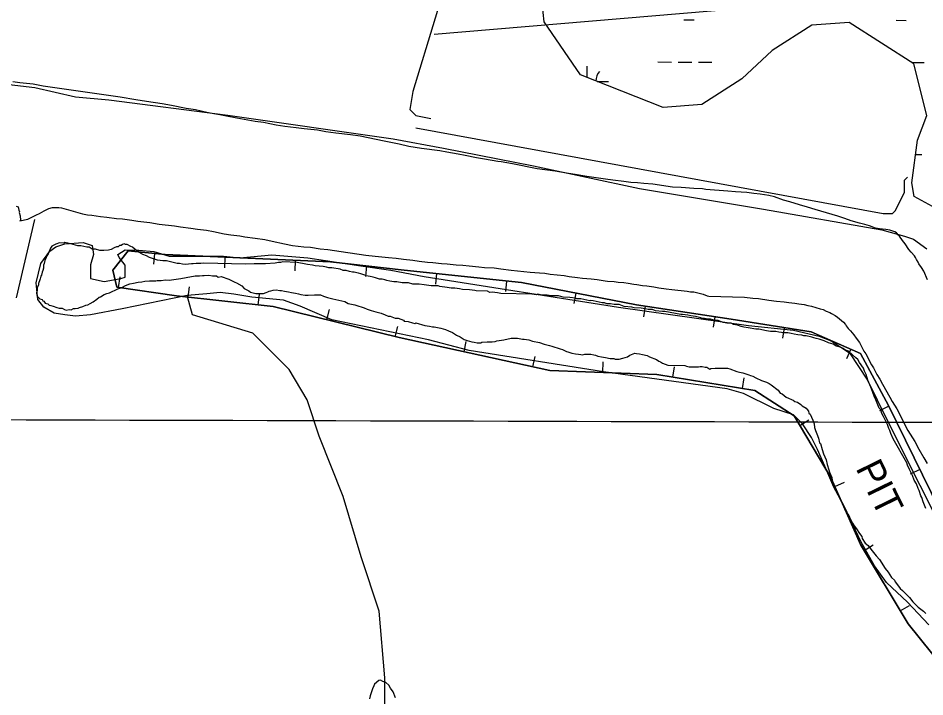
# Model space of a CAD drawing. Extents: x 3172297 to 3210190, y 958463 to 983887.
# Drawn here: x 3182176 to 3184322, y 975375 to 976980 of the extents above; entities that cross this region are included whole.
import ezdxf

# ---------------------------------------------------------------- set-up
doc = ezdxf.new("R2010")
doc.units = 0
for name, color, linetype in [('V-BORW-LINE', 7, 'Continuous'), ('V-GRID-MAJR', 7, 'Continuous'), ('V-RIVR-RANG', 7, 'Continuous'), ('V-SITE-VEGE', 7, 'Continuous'), ('V-TOPO-SHOR', 7, 'Continuous'), ('V-WETL-SWMP', 7, 'Continuous')]:
    doc.layers.add(name, color=color, linetype=linetype)

msp = doc.modelspace()

# ---------------------------------------------------------------- linework, layer by layer
at = {"layer": 'V-BORW-LINE'}
for p, q in [((3182498.8, 976423.5), (3182496.2, 976398.6)), ((3182665.1, 976414.7), (3182664, 976389.7)), ((3182831.6, 976407.4), (3182830.5, 976382.4)), ((3183000.7, 976394.1), (3182998, 976369.3)), ((3182413.6, 976343.3), (3182417.2, 976368.1)), ((3183166.3, 976376), (3183163.7, 976351.2)), ((3183332, 976358.4), (3183329.4, 976333.6)), ((3182578.5, 976320.1), (3182581.3, 976344.9)), ((3182744.1, 976301.8), (3182746.9, 976326.6)), ((3183496, 976329.7), (3183491.2, 976305.1)), ((3183659.7, 976298.8), (3183656, 976274.1)), ((3182906.7, 976266.6), (3182912.7, 976290.9)), ((3183824.5, 976274), (3183820.7, 976249.3)), ((3183068.5, 976226.8), (3183074.5, 976251.1)), ((3183989, 976248.1), (3183985.1, 976223.4)), ((3183231.2, 976191.2), (3183236.6, 976215.6)), ((3184146.3, 976197.1), (3184136.3, 976174.2)), ((3183394, 976155.8), (3183399.4, 976180.2)), ((3183559.6, 976142.1), (3183560.6, 976167.1)), ((3183725.6, 976130.9), (3183729.6, 976155.6)), ((3183890.1, 976104.5), (3183894.1, 976129.2)), ((3184236.6, 976062.6), (3184214.2, 976051.6)), ((3184025.7, 976017), (3184047.2, 976029.8)), ((3184309.6, 975912.8), (3184287.2, 975901.9)), ((3184108.7, 975872.7), (3184131.5, 975882.8)), ((3184178, 975721.3), (3184199.4, 975734.2)), ((3184263.6, 975578.4), (3184285, 975591.2))]:
    msp.add_line(p, q, dxfattribs=at)
for points in [[(3184396, 975406.6), (3184281.9, 975547.8), (3184169.7, 975735.2), (3184100, 975892.1), (3184012.5, 976039.3), (3183919.6, 976099.8), (3183687.3, 976137), (3183433.9, 976147.1), (3183078, 976224.5), (3182779.5, 976297.9), (3182551.1, 976323.1), (3182409.4, 976343.9), (3182400, 976383.8), (3182436.6, 976429.9), (3182524, 976420.9), (3182914.8, 976403.7)], [(3182914.8, 976403.7), (3182524, 976420.9), (3182436.6, 976429.9), (3182400, 976383.8), (3182409.4, 976343.9), (3182551.1, 976323.1), (3182779.5, 976297.9), (3183078, 976224.5), (3183433.9, 976147.1), (3183687.3, 976137), (3183919.6, 976099.8), (3184012.5, 976039.3), (3184100, 975892.1), (3184169.7, 975735.2), (3184281.9, 975547.8), (3184396, 975406.6)], [(3182914.8, 976403.7), (3183089.3, 976384.2), (3183367, 976354.7), (3183639.1, 976301.9), (3183863.3, 976268.1), (3184052.4, 976238), (3184169.3, 976187.1), (3184235.8, 976064.2), (3184336.3, 975858.1), (3184474.4, 975546.9), (3184589.7, 975345.9), (3184718, 975116), (3184852.9, 974871.7), (3184939.5, 974677.4), (3185118.5, 974284.7), (3185285.5, 973986.3), (3185406.5, 973754.8)], [(3185406.5, 973754.8), (3185285.5, 973986.3), (3185118.5, 974284.7), (3184939.5, 974677.4), (3184852.9, 974871.7), (3184718, 975116), (3184589.7, 975345.9), (3184474.4, 975546.9), (3184336.3, 975858.1), (3184235.8, 976064.2), (3184169.3, 976187.1), (3184052.4, 976238), (3183863.3, 976268.1), (3183639.1, 976301.9), (3183367, 976354.7), (3183089.3, 976384.2), (3182914.8, 976403.7)]]:
    msp.add_lwpolyline(points, dxfattribs=at)
at = {"layer": 'V-GRID-MAJR'}
msp.add_spline([(3176574.9, 976046.2), (3181787.8, 976031.4), (3187000.7, 976017.3), (3192213.6, 976004.1), (3197426.5, 975991.6), (3202639.4, 975979.8), (3207852.4, 975968.8)], degree=3, dxfattribs=at)
at = {"layer": 'V-SITE-VEGE'}
for points in [[(3182653.4, 976751.8), (3182639.3, 976754.2), (3182622.2, 976757.5), (3182595.7, 976763.1), (3182573.8, 976766.4), (3182538.7, 976773.6), (3182516.9, 976777.7), (3182479.5, 976783.4), (3182454.5, 976787.5), (3182417.1, 976793.2), (3182235.3, 976819.4), (3182211.2, 976824.2), (3182180, 976827.5), (3182163.6, 976830)], [(3184327.8, 976361.3), (3184319.4, 976381.7), (3184313.9, 976390.3), (3184307.8, 976398.9), (3184306.2, 976402.8), (3184301.6, 976409.1), (3184299.3, 976413.8), (3184297, 976417.7), (3184289.2, 976427.1), (3184283.8, 976433.4), (3184275.3, 976446.7), (3184269.1, 976454.6), (3184262.1, 976464.8), (3184259, 976467.1), (3184254.4, 976472.6), (3184250.5, 976475), (3184238.8, 976479), (3184229.4, 976480.6), (3184214.6, 976482.3), (3184205.3, 976483.9), (3184190.5, 976488.7), (3184179.6, 976491.9), (3184167.1, 976495.1), (3184147.6, 976500.7), (3184132, 976506.2), (3184115.7, 976511.8), (3184089.2, 976519.8), (3184061.9, 976527.8), (3184044, 976533.4), (3184025.3, 976539), (3184001.9, 976546.1), (3183987.1, 976550.1), (3183966.1, 976557.3), (3183952.8, 976560.5), (3183931.8, 976563.8), (3183916.9, 976565.4), (3183900.6, 976567.9), (3183874, 976569.6), (3183855.3, 976571.3), (3183803.8, 976574.8), (3183795.2, 976576.4), (3183774.9, 976577.3), (3183745.3, 976579.8), (3183724.2, 976580.8), (3183678.2, 976587.3), (3183656.3, 976589), (3183641.5, 976590.7), (3183625.9, 976591.6), (3183609.5, 976594), (3183583, 976597.3), (3183565.8, 976599.8), (3183521.4, 976605.5), (3183494.1, 976610.4), (3183473.8, 976613.7), (3183446.5, 976618.5), (3183404.4, 976624.3), (3183345.9, 976635.6), (3183319.4, 976640.4), (3183310.8, 976641.3), (3183279.6, 976647), (3183260.9, 976650.2), (3183233.6, 976655.8), (3183217.2, 976658.3), (3183190.7, 976663.2), (3183174.3, 976666.4), (3183130.7, 976672.1), (3183100.2, 976677), (3183077.6, 976681.9), (3183042.5, 976689.1), (3182985.6, 976701.2), (3182962.2, 976704.5), (3182927.9, 976708.6), (3182904.5, 976711.1), (3182884.2, 976715.1), (3182853, 976718.5), (3182834.3, 976720.9), (3182807, 976724.2), (3182786.7, 976727.5), (3182756.3, 976733.2), (3182736.8, 976735.6), (3182693.9, 976743.7), (3182669, 976748.6), (3182653.4, 976751.8)], [(3182171, 976535.2), (3182176.3, 976533.7), (3182177.4, 976525.8), (3182179.3, 976522.4), (3182178.6, 976520.5), (3182180.4, 976512.5), (3182181.5, 976502.5), (3182180.1, 976500.6), (3182198.7, 976504.8), (3182208.1, 976509.2), (3182219.5, 976514.8), (3182226.8, 976518), (3182237.6, 976524.3), (3182242.2, 976526.8), (3182248.9, 976530), (3182257.6, 976532.4), (3182272.1, 976532.7), (3182278.7, 976531.9), (3182328, 976517.5), (3182339.8, 976515.2), (3182350.4, 976514.3), (3182370.8, 976511.2), (3182386, 976509.5), (3182408.4, 976506.3), (3182422.9, 976505.3), (3182445.3, 976502.8), (3182459.2, 976500.4), (3182487.5, 976497.1), (3182509.9, 976493.3), (3182546.2, 976489.1), (3182560, 976486.8), (3182584.4, 976483.5), (3182600.2, 976481.2), (3182621.9, 976478.7), (3182638.4, 976475.6), (3182663.4, 976470.4), (3182679.2, 976468), (3182701, 976465.5), (3182712.8, 976463.2), (3182737.2, 976460), (3182759.6, 976456.8), (3182777.4, 976452.4), (3182806.3, 976446.4), (3182825.4, 976442.7), (3182852.4, 976439.4), (3182867.6, 976438.3), (3182890.7, 976434.5), (3182908.5, 976432.7), (3182940.1, 976428), (3182998.8, 976419.9), (3183021.2, 976417.4), (3183052.8, 976414), (3183070.7, 976412.9), (3183087.8, 976410.5), (3183110.2, 976408), (3183124.7, 976405.7), (3183144.5, 976403.2), (3183157.7, 976402.2), (3183178.1, 976399.7), (3183191.3, 976398.8), (3183212.4, 976396.9), (3183228.3, 976395.9), (3183243.4, 976394.2), (3183265.9, 976392.3), (3183279.7, 976390.7), (3183302.2, 976389.5), (3183318, 976387.1), (3183342.4, 976384.5), (3183387.9, 976379.5), (3183409.7, 976377.6), (3183422.2, 976377.3), (3183434.7, 976375), (3183468.4, 976371.6), (3183480.2, 976369.3), (3183500, 976366.8), (3183511.9, 976365.2), (3183532.3, 976363.4), (3183546.2, 976361.7), (3183565.3, 976359.3), (3183570.6, 976358.5), (3183586.4, 976357.5), (3183595.6, 976355.9), (3183609.5, 976354.9), (3183620, 976353.3), (3183633.2, 976351), (3183640.4, 976350.2), (3183653.6, 976347.9), (3183663.5, 976347), (3183680.6, 976344.6)], [(3183037.1, 976362.7), (3183031.5, 976362.8), (3183021.8, 976365.9), (3183016.2, 976367.4), (3183009.2, 976369), (3182999.4, 976370.6), (3182996.6, 976372.1), (3182986.9, 976375.2), (3182981.3, 976376.7), (3182977.1, 976378.2), (3182971.5, 976379.7), (3182967.3, 976379.8), (3182960.4, 976381.4), (3182952, 976383), (3182945, 976383.2), (3182938, 976386.2), (3182918.4, 976389.5), (3182911.4, 976389.6), (3182905.8, 976391.2), (3182897.5, 976392.8), (3182879.2, 976394.6), (3182872.3, 976396.2), (3182861.1, 976397.9), (3182856.9, 976398), (3182835.9, 976402.7), (3182802.2, 976403.5), (3182796.6, 976402.2), (3182792.4, 976402.3), (3182783.9, 976401.1), (3182761.4, 976398.9), (3182734.7, 976399.5), (3182713.7, 976398.6), (3182615.4, 976401), (3182608.4, 976399.8), (3182597.2, 976400), (3182590.1, 976398.8), (3182585.9, 976398.9), (3182571.8, 976397.8), (3182564.8, 976398), (3182557.8, 976399.6), (3182552.2, 976399.7), (3182527.1, 976405.9), (3182518.7, 976406.1), (3182506.1, 976407.8), (3182486.6, 976413.9), (3182479.7, 976418.3), (3182471.3, 976421.3), (3182465.8, 976424.3), (3182453.3, 976433), (3182446.5, 976438.8), (3182442.3, 976440.3), (3182434, 976444.7), (3182429.8, 976444.8), (3182427, 976446.3), (3182422.7, 976445), (3182419.9, 976442.2), (3182415.7, 976442.3), (3182412.8, 976439.6), (3182408.6, 976439.7), (3182402.9, 976437), (3182395.8, 976433), (3182390.1, 976431.7), (3182378.9, 976430.6), (3182369, 976430.8), (3182359.3, 976433.9), (3182350.9, 976434.1), (3182344, 976438.5), (3182338.3, 976438.6), (3182324.4, 976441.7), (3182317.4, 976441.9), (3182300.6, 976446.5), (3182286.7, 976449.7), (3182283.8, 976448.3), (3182274, 976448.6), (3182265.5, 976446), (3182255.6, 976440.6), (3182252.6, 976436.4), (3182246.7, 976422.5), (3182243.8, 976418.4), (3182242.3, 976414.2), (3182239.3, 976407.3), (3182237.7, 976400.3), (3182236.2, 976396.1), (3182236.1, 976389.1), (3182234.5, 976383.5), (3182233, 976379.4), (3182231.4, 976372.4), (3182230, 976369.6), (3182228.4, 976364), (3182227, 976361.2), (3182223.9, 976352.9), (3182223.8, 976348.7), (3182220.9, 976343.1), (3182220.7, 976336.1), (3182219.2, 976330.5), (3182220.5, 976324.9), (3182221.8, 976322.1), (3182227.3, 976316.3), (3182232.9, 976314.8), (3182234.2, 976311.9), (3182237, 976310.5)], [(3182259.1, 976298.7), (3182267.5, 976295.7), (3182273.1, 976294.1), (3182280.1, 976294), (3182285.6, 976291), (3182289.8, 976289.5), (3182296.9, 976290.8), (3182301.1, 976290.7), (3182306.7, 976293.3), (3182311, 976293.2), (3182318, 976294.5), (3182320.9, 976295.8), (3182329.3, 976298.4), (3182336.4, 976301), (3182340.7, 976302.3), (3182346.3, 976305), (3182353.5, 976309), (3182362.1, 976315.9), (3182367.8, 976319.9), (3182370.6, 976321.3), (3182379.2, 976326.7), (3182386.2, 976329.3), (3182391.9, 976330.6), (3182411.8, 976339.9), (3182418.9, 976342.6), (3182423.1, 976343.9), (3182430.2, 976347.9), (3182440.1, 976351.9), (3182448.6, 976353.1), (3182459.9, 976355.6), (3182468.3, 976356.8), (3182475.4, 976358), (3182486.7, 976359.2), (3182502.1, 976358.8), (3182504.9, 976360.1), (3182514.8, 976359.9), (3182524.6, 976361.1), (3182533, 976360.9), (3182561.2, 976364.4), (3182573.9, 976366.9), (3182595, 976370.6), (3182604.9, 976370.4), (3182611.9, 976371.6), (3182616.1, 976371.5), (3182627.4, 976372.6), (3182635.8, 976371), (3182645.6, 976370.8), (3182649.7, 976367.9), (3182656.8, 976369.1), (3182674.9, 976363.1), (3182688.8, 976355.7), (3182692.9, 976354.2), (3182705.4, 976346.9), (3182710.9, 976341.1), (3182722, 976335.2), (3182726.1, 976332.3), (3182738.7, 976329.2), (3182756.9, 976328.8), (3182762.6, 976331.4), (3182766.8, 976332.7), (3182769.7, 976334.1), (3182773.9, 976335.4), (3182779.6, 976336.7), (3182786.6, 976337.9), (3182795, 976336.3), (3182799.2, 976336.2), (3182806.2, 976334.6), (3182816, 976333), (3182823, 976331.4), (3182832.7, 976329.7), (3182839.7, 976328.2), (3182845.3, 976326.6), (3182855.1, 976325), (3182862.1, 976324.8), (3182877.6, 976325.9), (3182891.6, 976325.5), (3182898.6, 976322.5), (3182908.3, 976319.5), (3182920.9, 976316.4), (3182948.8, 976310.1), (3182957.1, 976305.7), (3182972.5, 976302.5), (3182975.3, 976301), (3182994.8, 976294.9), (3183001.7, 976292), (3183011.5, 976288.9), (3183022.6, 976285.8), (3183035.2, 976282.7), (3183044.9, 976278.3), (3183051.9, 976275.3), (3183056.1, 976275.2), (3183068.6, 976270.7), (3183075.6, 976270.5), (3183088.1, 976266), (3183089.5, 976263.2), (3183099.3, 976262.9), (3183109.1, 976259.9), (3183114.6, 976258.3), (3183117.5, 976259.7), (3183138.4, 976253.6), (3183149.6, 976251.9)], [(3184111.6, 976204.7), (3184104.7, 976209.1), (3184093.5, 976212.2), (3184083.8, 976216.7), (3184071.3, 976221.2), (3184064.3, 976222.7), (3184058.7, 976224.3), (3184054.6, 976225.8), (3184040.6, 976228.9), (3184035, 976229.1), (3184030.8, 976230.6), (3184021, 976230.8), (3184012.6, 976232.4), (3184005.6, 976234), (3183997.2, 976235.6), (3183988.8, 976235.8), (3183976.2, 976237.5), (3183969.2, 976239.1), (3183956.6, 976239.4), (3183946.8, 976241), (3183928.6, 976244.3), (3183921.6, 976244.4), (3183903.4, 976247.7), (3183893.7, 976249.3), (3183886.7, 976250.9), (3183878.3, 976253.9), (3183868.5, 976255.6), (3183863, 976258.5), (3183853.2, 976258.7), (3183844.8, 976260.3), (3183832.3, 976264.9), (3183825.2, 976265), (3183814.1, 976268.1), (3183808.5, 976268.2), (3183800.1, 976269.8), (3183794.5, 976270), (3183791.7, 976271.5), (3183779.1, 976274.6), (3183767.9, 976276.2), (3183761, 976277.8), (3183748.4, 976279.5), (3183744.2, 976279.6), (3183719, 976284.4), (3183706.4, 976286.2), (3183700.8, 976286.3), (3183684, 976288.1), (3183677, 976291.1), (3183667.2, 976291.3), (3183660.2, 976292.9), (3183650.4, 976294.5), (3183633.6, 976294.9), (3183628, 976296.5), (3183609.8, 976298.3), (3183598.7, 976302.8), (3183586.1, 976303.1), (3183577.7, 976304.7), (3183569.3, 976304.9), (3183563.7, 976306.5), (3183558.1, 976306.6), (3183537.1, 976311.3), (3183531.6, 976312.8), (3183528.7, 976311.5), (3183507.8, 976316.2), (3183497.9, 976316.5), (3183495.2, 976317.9), (3183481.2, 976319.7), (3183465.7, 976320.1), (3183454.6, 976323.1), (3183437.7, 976323.5), (3183427.9, 976325.2), (3183412.5, 976325.6), (3183405.5, 976327.1), (3183402.7, 976325.8), (3183391.5, 976327.5), (3183318.5, 976329.2), (3183310.1, 976330.8), (3183297.5, 976332.5), (3183291.9, 976331.3), (3183286.4, 976334.2), (3183259.7, 976334.9), (3183256.9, 976336.3), (3183244.3, 976338), (3183227.5, 976338.5), (3183220.5, 976340), (3183209.3, 976341.7), (3183200.9, 976341.9), (3183191.1, 976343.5), (3183174.3, 976345.4), (3183170.1, 976346.9), (3183153.3, 976347.3), (3183136.5, 976349.1), (3183125.3, 976350.8), (3183109.9, 976351.1), (3183100.1, 976354.2), (3183084.7, 976354.5), (3183072.1, 976356.3), (3183065.1, 976356.4), (3183055.3, 976358.1), (3183048.3, 976359.6), (3183044.1, 976361.1), (3183037.1, 976362.7)], [(3183680.6, 976344.6), (3183691.8, 976342.4), (3183709.6, 976339.9), (3183722.8, 976338.3), (3183759.1, 976334.1), (3183767.4, 976332.8), (3183774.7, 976332.6), (3183797, 976327.4), (3183806.2, 976323.2), (3183810.8, 976322.5), (3183894.7, 976320.4), (3183914.5, 976318), (3183928.4, 976317), (3183952.7, 976313.1), (3183970.5, 976310.7), (3183989, 976308.9), (3183999.5, 976307.3), (3184014.1, 976306.3), (3184023.3, 976304.8), (3184035.8, 976303.1), (3184045, 976300.9), (3184053.5, 976298.7), (3184073.9, 976292.3), (3184081.1, 976290.8), (3184088.3, 976287.3), (3184096.8, 976283.8), (3184100.7, 976281.7), (3184109.2, 976276.9), (3184115.1, 976272.8), (3184124.8, 976265.3), (3184129.3, 976261.2), (3184133.8, 976255.8), (3184135.7, 976252.5), (3184140.2, 976246.4), (3184145.4, 976240.3), (3184153.7, 976231.5), (3184158.8, 976223.5), (3184167.2, 976212.7), (3184177.3, 976192.6), (3184181.7, 976185.9), (3184195.7, 976160.4), (3184200.1, 976153), (3184208.3, 976137.6), (3184215.3, 976126.2), (3184221.7, 976114.2), (3184238.8, 976084), (3184244.5, 976073.3), (3184255.3, 976056.5), (3184281.8, 976004.9), (3184298.4, 975978.7), (3184307.2, 975960.7), (3184319.3, 975939.9), (3184326.9, 975926.5)], [(3182237, 976310.5), (3182239.7, 976306.2), (3182246.6, 976304.6), (3182249.4, 976301.7), (3182253.6, 976300.2), (3182259.1, 976298.7)], [(3183149.6, 976251.9), (3183156.6, 976250.3), (3183160.8, 976250.2), (3183176.1, 976247), (3183187.3, 976244), (3183194.2, 976241), (3183204, 976236.5), (3183213.7, 976230.7), (3183222, 976226.3), (3183231.7, 976220.4), (3183238.6, 976217.4), (3183249.8, 976214.4), (3183255.4, 976214.2), (3183262.4, 976212.6), (3183270.8, 976212.4), (3183273.6, 976213.8), (3183286.3, 976214.9), (3183297.5, 976214.6), (3183304.6, 976215.8), (3183308.8, 976217.1), (3183325.7, 976219.5), (3183342.6, 976223.3), (3183358.1, 976223), (3183369.3, 976221.3), (3183373.5, 976221.2), (3183384.7, 976219.5), (3183393, 976216.5), (3183409.8, 976213.3), (3183420.9, 976208.8), (3183433.5, 976205.7), (3183439.1, 976204.2), (3183458.6, 976198.1), (3183464.1, 976196.5), (3183473.9, 976192.1), (3183476.6, 976190.6), (3183486.4, 976187.6), (3183494.8, 976186), (3183501.8, 976185.8), (3183507.4, 976184.3), (3183511.6, 976184.2), (3183517.2, 976185.4), (3183531.3, 976185.1), (3183538.2, 976183.5), (3183542.5, 976183.4), (3183548, 976180.5), (3183556.4, 976178.9), (3183566.2, 976177.2), (3183577.4, 976175.5), (3183585.8, 976175.3), (3183588.6, 976173.9), (3183598.4, 976173.6), (3183606.9, 976176.2), (3183618.2, 976178.8), (3183623.9, 976182.8), (3183635.2, 976188.2), (3183639.4, 976186.7), (3183646.4, 976186.5), (3183653.4, 976184.9), (3183664.6, 976181.9), (3183670.1, 976178.9), (3183686.8, 976172.9), (3183692.3, 976168.6), (3183696.5, 976167), (3183700.7, 976164.1), (3183713.2, 976159.6), (3183753.9, 976158.6), (3183758, 976157.1), (3183763.6, 976155.6), (3183786.1, 976155.1), (3183790.3, 976156.4), (3183794.5, 976156.3), (3183801.5, 976154.7), (3183805.7, 976154.6), (3183812.6, 976150.2), (3183815.5, 976151.5), (3183825.3, 976152.7), (3183854.8, 976152), (3183860.4, 976150.5), (3183877.1, 976144.4), (3183882.7, 976142.9), (3183891, 976141.3), (3183905, 976136.7), (3183909.2, 976135.2), (3183914.7, 976133.7), (3183921.6, 976129.3), (3183935.5, 976123.4), (3183946.7, 976118.9), (3183953.6, 976115.9), (3183957.8, 976113), (3183974.3, 976100), (3183979.7, 976092.8), (3183983.9, 976091.3), (3183993.6, 976084), (3183999.1, 976081.1), (3184006.1, 976078.1), (3184010.2, 976076.6), (3184014.4, 976073.7), (3184020, 976072.2), (3184028.2, 976066.4), (3184031, 976063.5), (3184040.7, 976057.6)], [(3184324.2, 975820.5), (3184317.5, 975836.1), (3184314.9, 975846), (3184312.2, 975850.3), (3184308.3, 975863), (3184305.6, 975867.3), (3184301.7, 975878.6), (3184296.3, 975887.2), (3184292.3, 975898.5), (3184285.7, 975912.7), (3184280.3, 975922.7), (3184279, 975928.3), (3184246.7, 975985.3), (3184241.4, 975998), (3184238.8, 976005.1), (3184236.1, 976009.4), (3184233.5, 976019.3), (3184224.1, 976037.8), (3184220.1, 976044.9), (3184217.5, 976053.4), (3184213.4, 976057.7), (3184205.4, 976077.5), (3184201.4, 976086), (3184198.8, 976094.5), (3184193.5, 976107.3), (3184186.9, 976124.3), (3184183, 976137), (3184179, 976145.6), (3184176.3, 976152.6), (3184166.8, 976165.5), (3184162.8, 976172.6), (3184158.7, 976176.9), (3184150.4, 976184.2), (3184140.8, 976192.8), (3184132.5, 976195.8), (3184128.3, 976198.7), (3184121.4, 976201.7), (3184115.8, 976203.2), (3184111.6, 976204.7)], [(3184040.7, 976057.6), (3184043.4, 976054.8), (3184046.1, 976050.5), (3184047.4, 976046.2), (3184050.1, 976043.4), (3184056.8, 976029.2), (3184059.4, 976020.7), (3184060.6, 976012.2), (3184063.3, 976005.1), (3184065.9, 975996.7), (3184069.8, 975986.7), (3184072.4, 975975.4), (3184075.1, 975974), (3184079, 975959.8), (3184081.6, 975949.9), (3184088.3, 975935.7), (3184090.8, 975924.4), (3184094.7, 975911.7), (3184096, 975906.1), (3184101.3, 975893.3), (3184102.5, 975887.7), (3184105.1, 975877.8), (3184107.8, 975873.5), (3184113.1, 975859.3), (3184117.1, 975850.8), (3184123.8, 975836.6), (3184126.5, 975832.3), (3184131.8, 975819.6), (3184134.4, 975812.5), (3184139.9, 975806.7), (3184146.6, 975792.5), (3184150.6, 975785.4), (3184154.7, 975779.7), (3184160.1, 975772.5), (3184166.9, 975761.1), (3184172.3, 975754), (3184173.6, 975749.7), (3184180.4, 975738.3), (3184187.2, 975732.6), (3184194.1, 975724), (3184206.3, 975708.2), (3184214.5, 975699.6), (3184228.1, 975678.2), (3184234.9, 975669.6), (3184243, 975656.8), (3184249.9, 975651), (3184251.2, 975646.8), (3184259.3, 975636.7), (3184263.4, 975631), (3184268.9, 975626.7), (3184285.4, 975609.4), (3184293.5, 975599.4), (3184305.9, 975586.5), (3184318.3, 975577.8), (3184323.8, 975572)], [(3183069, 975372.7), (3183063.8, 975386.9), (3183057, 975395.5), (3183052.9, 975402.6), (3183046, 975408.4), (3183039.1, 975411.4), (3183033.5, 975414.3), (3183029.3, 975413), (3183019.3, 975404.8), (3183017.8, 975400.6), (3183014.8, 975393.7), (3183008.8, 975377), (3183007.2, 975370)]]:
    msp.add_lwpolyline(points, dxfattribs=at)
at = {"layer": 'V-TOPO-SHOR'}
msp.add_line((3183160.2, 976942.5), (3185867.7, 977171.5), dxfattribs=at)
for points in [[(3183454.5, 977506), (3183361.5, 977470.6), (3183297.1, 977427.9), (3183268.3, 977327.9), (3183109.9, 976807), (3183102.7, 976764.1), (3183116.9, 976749.8), (3183152.6, 976742.6)], [(3181904.8, 976852.8), (3182215.4, 976816.3), (3182311.8, 976794.6), (3182390.3, 976787.3), (3182672.3, 976750.9), (3183063.2, 976694.6), (3183182.8, 976672.9), (3183395.2, 976631.3), (3183646.8, 976577.1), (3183939.5, 976528.2), (3184219.7, 976479.3), (3184273.2, 976464.8), (3184294.6, 976457.6), (3184326.7, 976434.3)], [(3183116.8, 976721.2), (3184223.4, 976518.5), (3184244.8, 976518.5), (3184252, 976525.6), (3184273.5, 976568.4), (3184273.5, 976582.7), (3184273.6, 976597), (3184280.7, 976604.1)], [(3182214.4, 976504.2), (3182171.1, 976318.6)], [(3184330.8, 975545.1), (3184280.9, 975598.8), (3184231, 975645.4), (3184202.6, 975684.7), (3184170.6, 975742), (3184131.5, 975824.2), (3184106.6, 975870.7), (3184085.3, 975920.7), (3184067.5, 975960), (3184053.3, 975988.6), (3184032, 976020.8), (3184010.6, 976042.3), (3183964.2, 976056.7), (3183892.9, 976092.6), (3183853.6, 976103.4), (3183560.9, 976143.4), (3183243.2, 976194.2), (3183146.8, 976219.4), (3182918.4, 976266.4), (3182843.5, 976298.7), (3182804.3, 976313.1), (3182729.3, 976320.5), (3182686.5, 976327.7), (3182654.3, 976331.4), (3182622.2, 976327.9), (3182575.7, 976324.4), (3182422.1, 976292.6), (3182347.1, 976278.5), (3182311.4, 976275.1), (3182286.4, 976278.7), (3182261.4, 976282.3), (3182236.4, 976296.7), (3182222.2, 976314.6), (3182218.7, 976353.9), (3182229.5, 976400.3), (3182251, 976428.8), (3182265.3, 976439.4), (3182286.8, 976446.5), (3182329.6, 976450), (3182351.1, 976442.8), (3182354.6, 976421.4), (3182347.4, 976396.4), (3182347.3, 976378.5), (3182347.3, 976364.3), (3182379.4, 976357), (3182418.7, 976364.1), (3182429.4, 976367.6), (3182429.5, 976396.2), (3182415.3, 976414.1), (3182411.7, 976421.2), (3182429.6, 976431.9), (3182461.7, 976431.8), (3182497.4, 976428.2), (3182533.1, 976417.4), (3182586.7, 976417.2), (3182661.7, 976417), (3182700.9, 976413.4), (3182776, 976420.3), (3182861.6, 976413), (3182986.6, 976394.8), (3183058, 976383.9), (3183136.5, 976369.4), (3183597, 976296.9), (3183904, 976253.3), (3184011.1, 976242.3), (3184071.8, 976227.9), (3184100.3, 976217.1), (3184143.1, 976188.4), (3184185.8, 976124), (3184232, 976031.1), (3184388.3, 975720)], [(3183043.5, 975277.2), (3183043.9, 975420), (3183030, 975577.2), (3182987.5, 975705.9), (3182945, 975848.8), (3182888.2, 975991.8), (3182859.8, 976077.6), (3182817.1, 976149.2), (3182774.4, 976192.1), (3182731.6, 976235.1), (3182588.9, 976278.3), (3182575.7, 976324.4)]]:
    msp.add_lwpolyline(points, dxfattribs=at)
at = {"layer": 'V-WETL-SWMP'}
for p, q in [((3183751.6, 976976.5), (3183775.6, 976976.4)), ((3184253.6, 976975.3), (3184277.6, 976975.2)), ((3183690, 976876.7), (3183722, 976876.6)), ((3183738, 976876.5), (3183770, 976876.5)), ((3183786, 976876.4), (3183818, 976876.3)), ((3184291.8, 976875.2), (3184319.9, 976875.1)), ((3183522.8, 976839.8), (3183522.9, 976866.6)), ((3183546.3, 976830.6), (3183572.8, 976830.5)), ((3184299.6, 976657.9), (3184314.8, 976657.9))]:
    msp.add_line(p, q, dxfattribs=at)
msp.add_lwpolyline([(3184348.3, 976530.1), (3184296.8, 976558.5), (3184291, 976591), (3184304, 976691.9), (3184326.6, 976750.2), (3184295.8, 976872.6), (3184142.8, 976970.2), (3184054, 976963.7), (3183960, 976903.9), (3183888.9, 976836.8), (3183794.2, 976776.3), (3183702.2, 976769.3), (3183507, 976846.1), (3183420.7, 976971.8), (3183413.8, 977038.7)], dxfattribs=at)
msp.add_arc((3183578.1, 976831), 35.2, 139.0865, 178.4339, dxfattribs=at)

# ---------------------------------------------------------------- texts
at = {"layer": 'V-RIVR-RANG'}
msp.add_text('PIT', height=64, rotation=296.0711, dxfattribs=at).set_placement((3184157, 975916))

doc.saveas('drawing.dxf')
